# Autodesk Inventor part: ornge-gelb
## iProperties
Created: 2004-10
Part Number: ornge-gelb
Document SubType Name: Modeling
Designer: sahrens
Manufacturer: Standard
Standards Organization: Custom
Author: sahrens
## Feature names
1. Extrusion1
2. Rundung2 [Fillet]
